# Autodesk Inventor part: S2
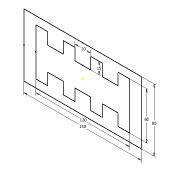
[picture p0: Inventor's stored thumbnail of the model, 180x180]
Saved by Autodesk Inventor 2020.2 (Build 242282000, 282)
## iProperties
Created: 2013-12
Part Number: S2
Material: Ogólny
Document SubType Name: Modeling
Designer: F.Stasiak
Density: 1 g/cm^3
Appearance: Domyślna
Manager: www.cadconsulting.pl
Company: Fabian Stasiak CAD Consulting
Author: F.Stasiak
Subject: Zbiór ćwiczeń. Autodesk Inventor 2020. Kurs podstawowy
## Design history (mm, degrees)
sketch "Szkic1"
  geometry: L1 (-75, 40)-(75, 40); L2 (75, 40)-(75, -40); L3 (75, -40)-(-75, -40); L4 (-75, -40)-(-75, 40); L5 (-60, 30)-(-60, -30); L6 (60, -30)-(60, 30); L7 (-10, 30)-(-10, 15); L8 (-10, 15)-(10, 15); L9 (10, 15)-(10, 30); L10 (-45, 30)-(-45, 15); L11 (-45, 15)-(-25, 15); L12 (-25, 15)-(-25, 30); L13 (-10, 30)-(-25, 30); L14 (-45, 30)-(-60, 30); L15 (25, 30)-(25, 15); L16 (25, 15)-(45, 15); L17 (45, 15)-(45, 30); L18 (60, 30)-(45, 30); L19 (25, 30)-(10, 30); L20 (-45, -30)-(-45, -15); L21 (-45, -15)-(-25, -15); L22 (-25, -15)-(-25, -30); L23 (-10, -30)-(-10, -15); L24 (-10, -15)-(10, -15); L25 (10, -15)-(10, -30); L26 (25, -30)-(25, -15); L27 (25, -15)-(45, -15); L28 (45, -15)-(45, -30); L29 (45, -30)-(60, -30); L30 (10, -30)-(25, -30); L31 (-60, -30)-(-45, -30); L32 (-25, -30)-(-10, -30); 5 further points
  constraints: 64 end point, 35 perpendicular, 22 collinear, 22 parallel, 4 midpoint, 2 horizontal, 2 horizontal alignment, 2 vertical alignment
  dimensions: "d2" = 150 distance of L2.end L3.end; "d3" = 80 distance of L1.end L2.end; "d5" = 20 distance between parallel lines of L9 L7; "d6" = 15 distance of L8.end L9.end; "d17" = 120 distance between parallel lines of L6 L5; "d18" = 60 distance between parallel lines of L18 L29
